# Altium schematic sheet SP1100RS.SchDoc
size D; SheetNumber: 0; SheetTotal: 0
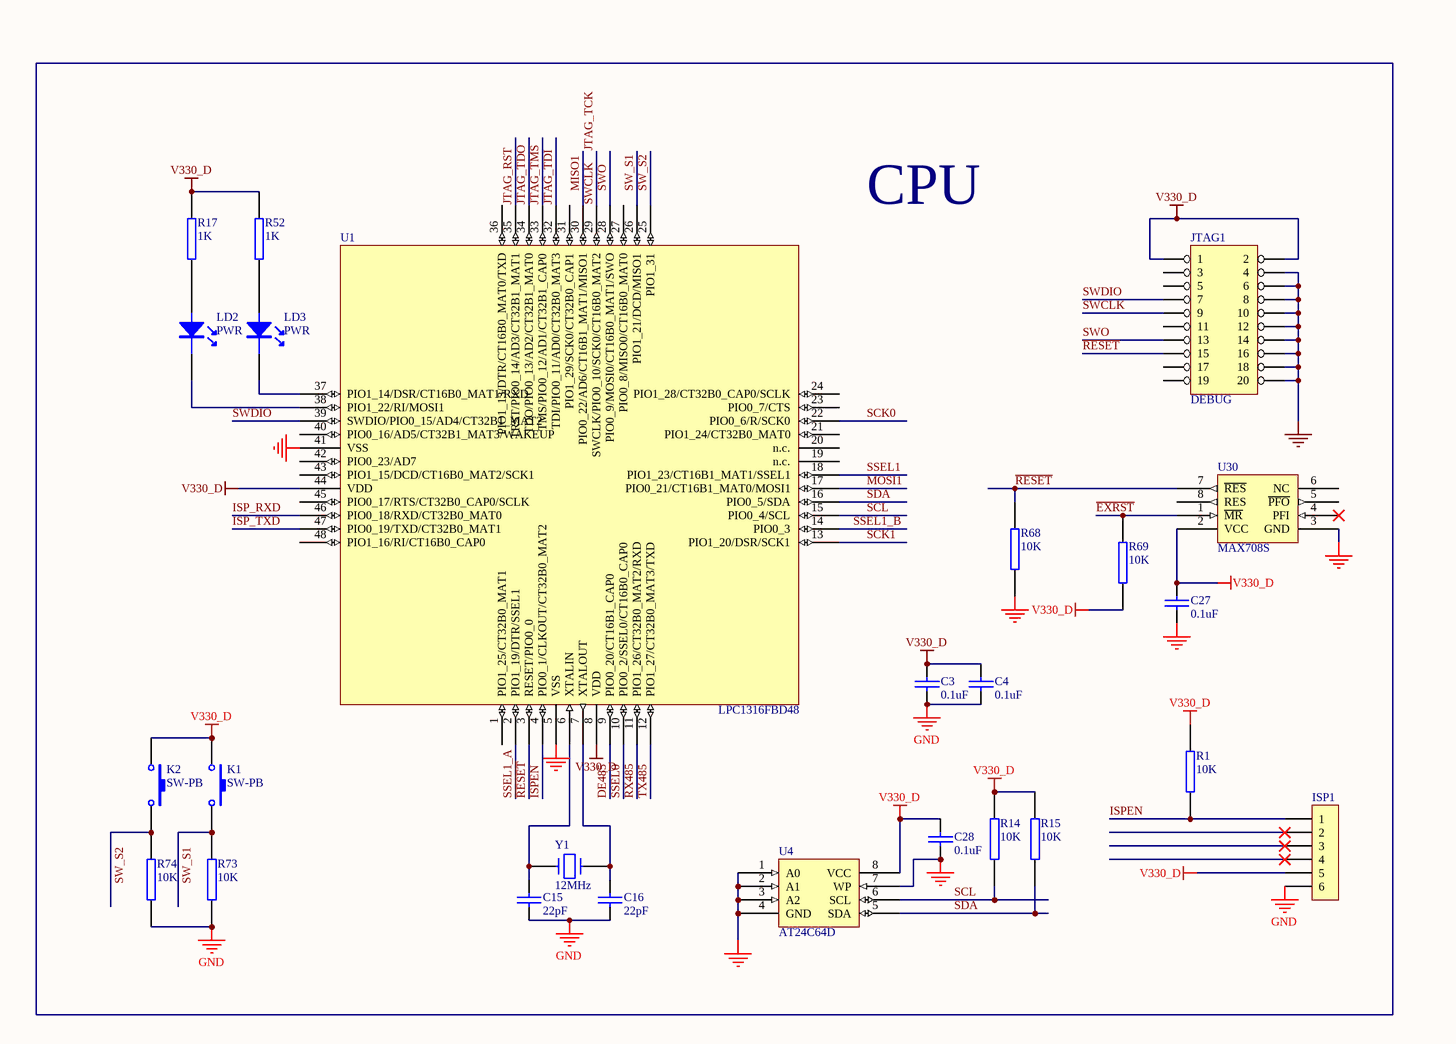
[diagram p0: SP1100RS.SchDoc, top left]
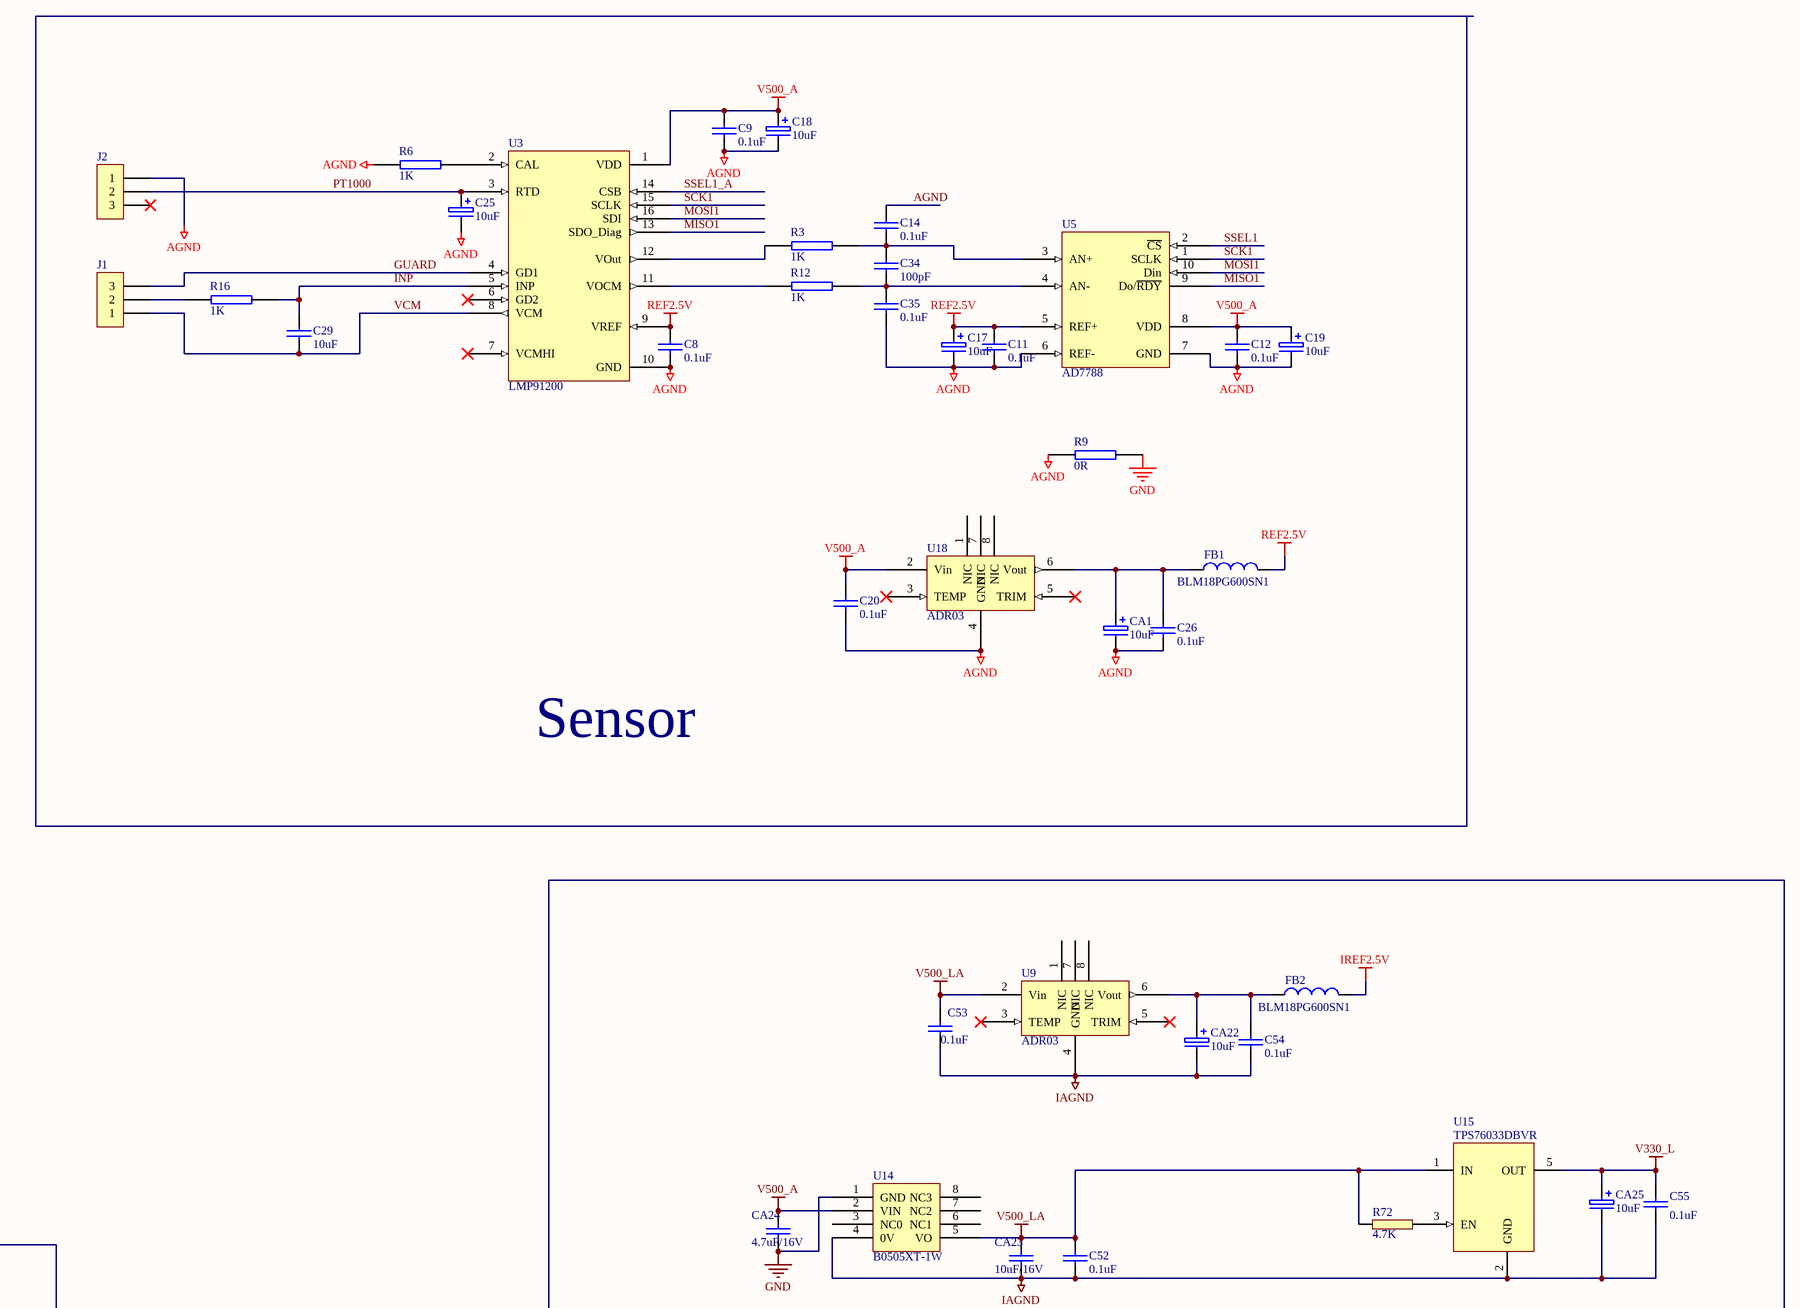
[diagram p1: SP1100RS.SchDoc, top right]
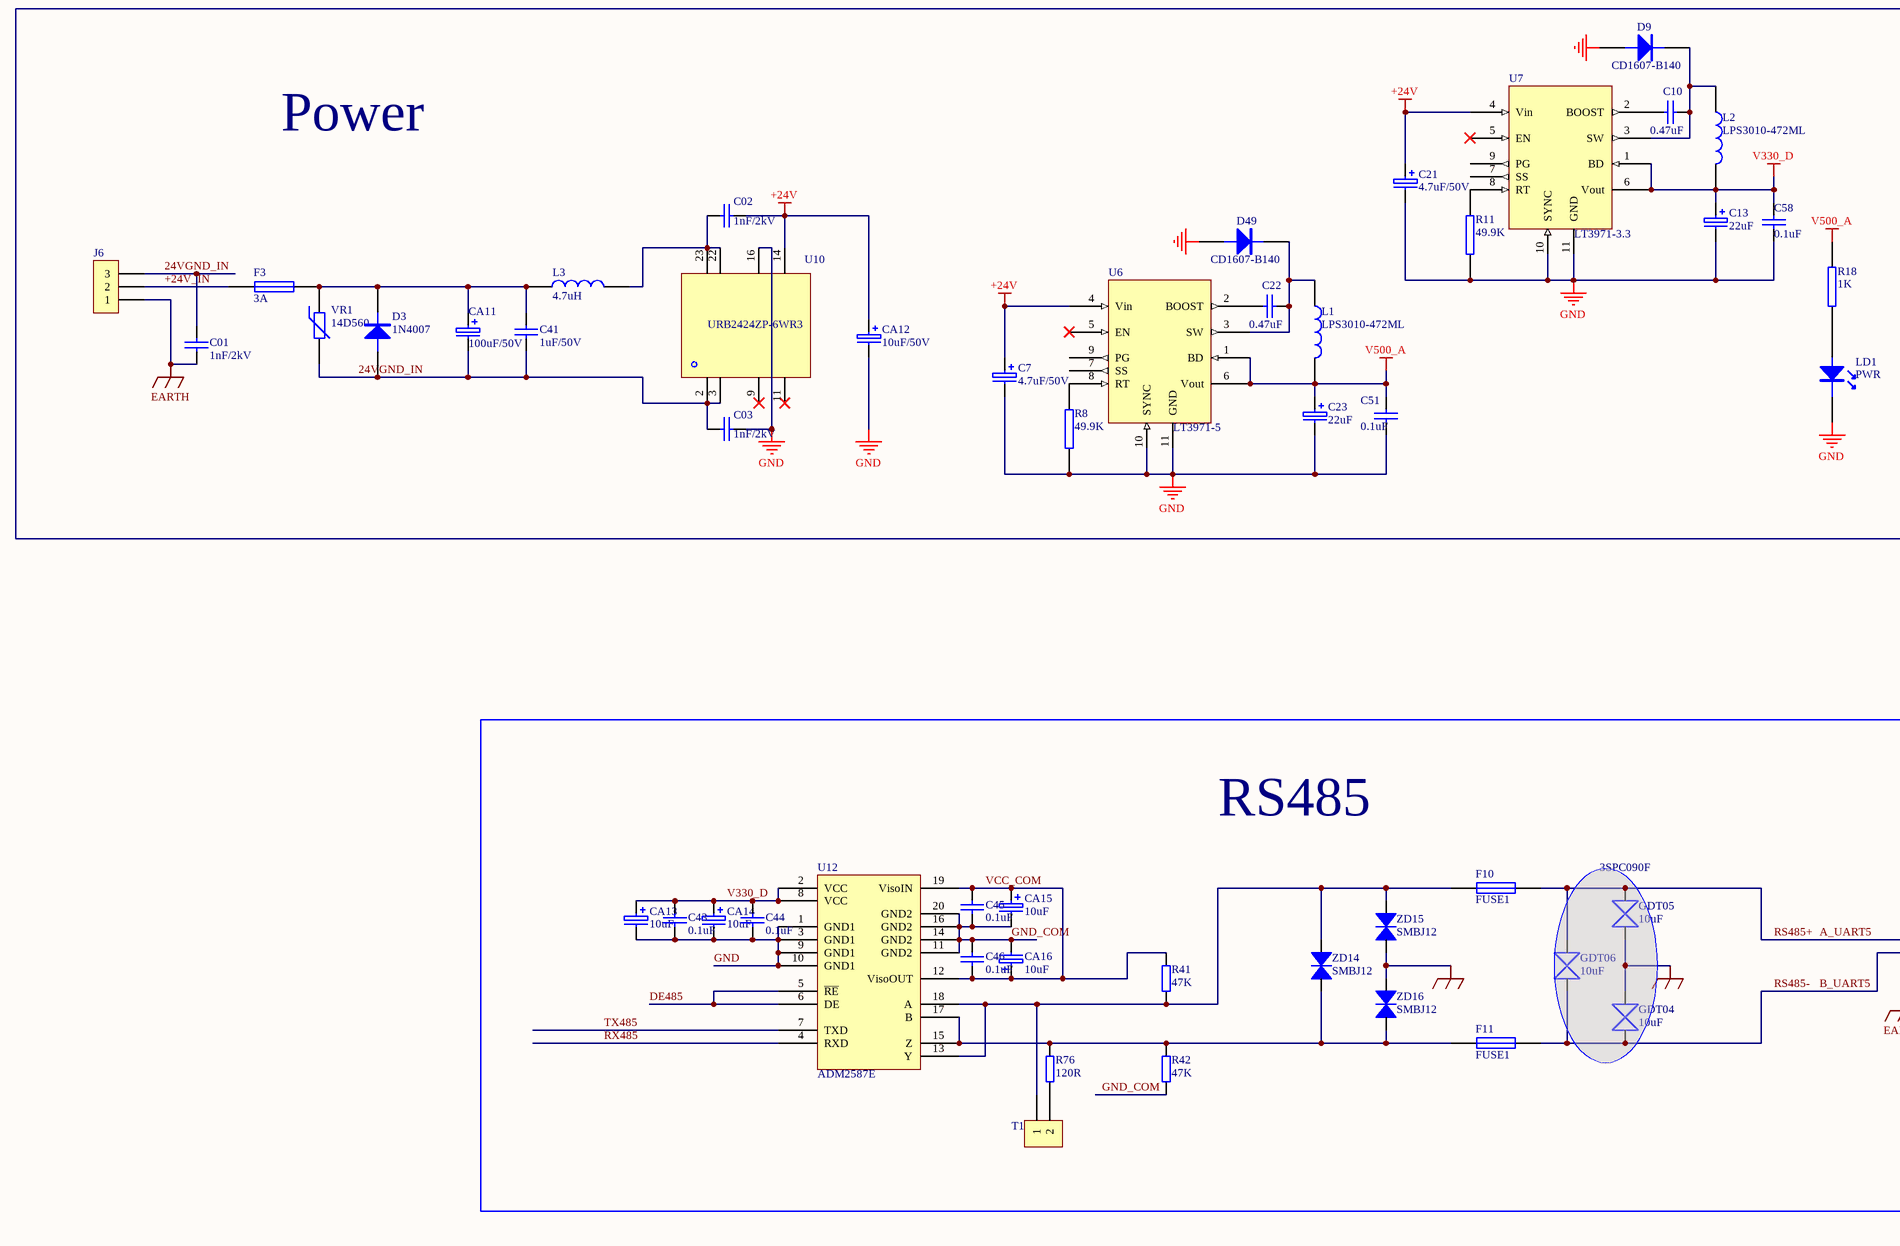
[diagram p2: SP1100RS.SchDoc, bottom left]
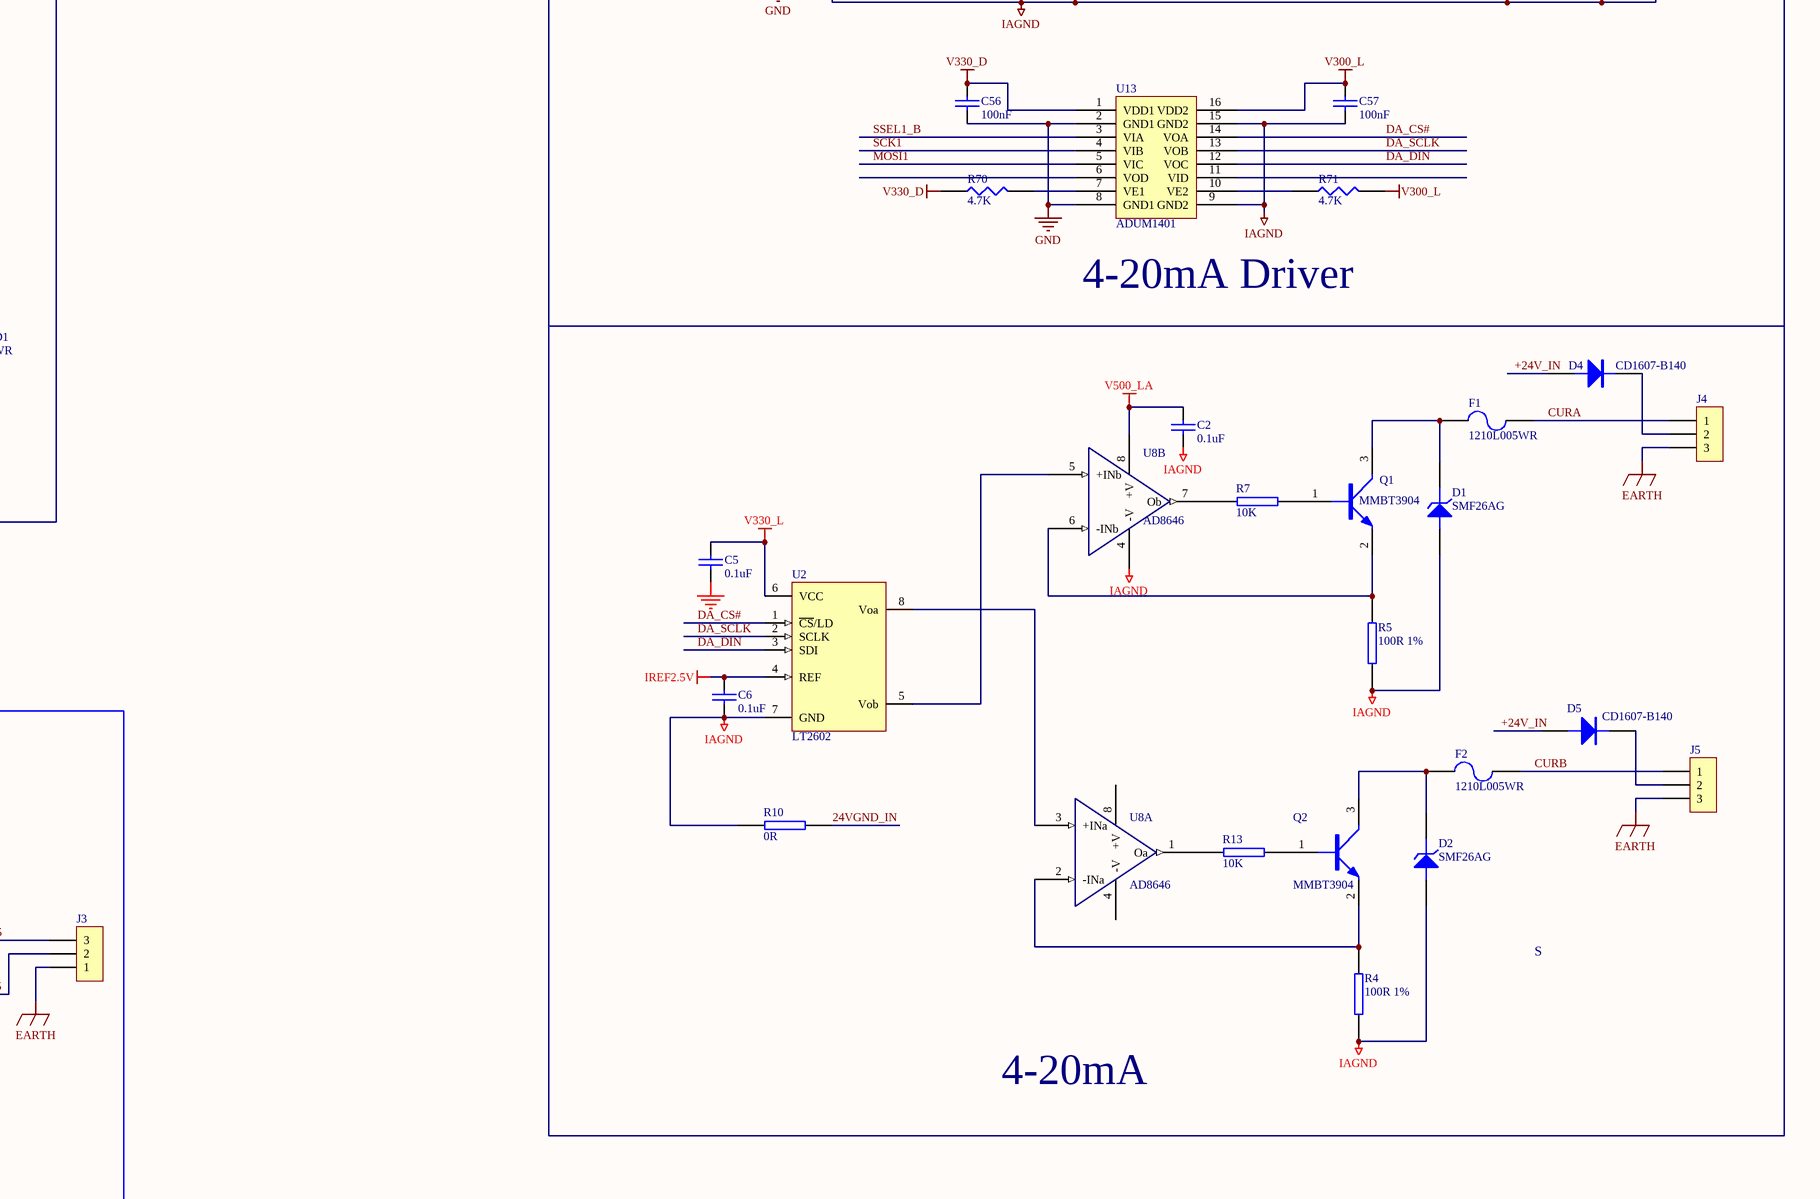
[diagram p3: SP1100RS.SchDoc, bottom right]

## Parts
C01  1nF/2kV
C2  0.1uF  [0603]
C02  1nF/2kV
C3  0.1uF  [0603]
C03  1nF/2kV
C4  0.1uF  [0603]
C5  0.1uF  [0603A]
C6  0.1uF  [0603A]
C7  4.7uF/50V  [1206C]
C8  0.1uF  [0603A]
C9  0.1uF  [0603]
C10  0.47uF  [0603]
C11  0.1uF  [0603]
C12  0.1uF  [0603]
C13  22uF  [1206C]
C14  0.1uF  [0603]
C15  22pF  [0603]
C16  22pF  [0603]
C17  10uF  [1206C]
C18  10uF  [1206C]
C19  10uF  [1206C]
C20  0.1uF  [0603A]
C21  4.7uF/50V  [1206C]
C22  0.47uF  [0603]
C23  22uF  [1206C]
C25  10uF  [1206C]
C26  0.1uF  [0603A]
C27  0.1uF  [0402]
C28  0.1uF  [0603]
C29  10uF  [1206C]
C34  100pF  [0603]
C35  0.1uF  [0603]
C41  1uF/50V  [0603]
C43  0.1uF  [0603]
C44  0.1uF  [0603]
C45  0.1uF  [0603]
C46  0.1uF  [0603]
C51  0.1uF
C52  0.1uF
C53  0.1uF  [0603A]
C54  0.1uF
C55  0.1uF  [0603A]
C56  100nF  [0603A]
C57  100nF  [0603A]
C58  0.1uF
CA1  10uF  [1206C]
CA11  100uF/50V  [1206C]
CA12  10uF/50V  [1206C]
CA13  10uF  [1206C]
CA14  10uF  [1206C]
CA15  10uF  [1206C]
CA16  10uF  [1206C]
CA22  10uF  [1206C]
CA23  10uF/16V
CA24  4.7uF/16V
CA25  10uF  [1206C]
D1  SMF26AG  [1206D]
D2  SMF26AG  [1206D]
D3  1N4007  [1206D]
D4  CD1607-B140  [1206D]
D5  CD1607-B140  [1206D]
D9  CD1607-B140  [1206D]
D49  CD1607-B140  [1206D]
F1  1210L005WR  [1206]
F2  1210L005WR  [1206]
F3  3A
F10  FUSE1
F11  FUSE1
FB1  BLM18PG600SN1  [0402-A]
FB2  BLM18PG600SN1  [0402-A]
GDT04  10uF  [1812]
GDT05  10uF  [1812]
GDT06  10uF  [1812]
ISP1  (no value)  [PH3-S]
J1  (no value)
J2  (no value)
J3  (no value)
J4  (no value)
J5  (no value)
J6  (no value)
JTAG1  DEBUG  [IDC20]
K1  SW-PB  [SPST-2]
K2  SW-PB  [SPST-2]
L1  LPS3010-472ML  [LPS3010]
L2  LPS3010-472ML  [LPS3010]
L3  4.7uH  [LPS3010]
LD1  PWR  [0603]
LD2  PWR  [0603]
LD3  PWR  [0603]
Q1  MMBT3904  [SOT-23]
Q2  MMBT3904  [SOT-23]
R1  10K  [0603]
R3  1K  [0603]
R4  100R 1%  [0603]
R5  100R 1%  [0603]
R6  1K  [0603]
R7  10K  [0603]
R8  49.9K  [0603]
R9  0R  [0603]
R10  0R  [0603]
R11  49.9K  [0603]
R12  1K  [0603]
R13  10K  [0603]
R14  10K  [0603]
R15  10K  [0603]
R16  1K  [0603]
R17  1K  [0603]
R18  1K  [0603]
R41  47K  [0603]
R42  47K  [0603]
R52  1K  [0603]
R68  10K  [0603]
R69  10K  [0603]
R70  4.7K  [0603A]
R71  4.7K  [0603A]
R72  4.7K  [0603A]
R73  10K  [0603]
R74  10K  [0603]
R76  120R  [0603]
T1  (no value)
U1  LPC1316FBD48  [0603]
U2  LT2602  [0603]
U3  LMP91200  [0603]
U4  AT24C64D  [SO-8]
U5  AD7788  [AD7788BRM]
U6  LT3971-5  [0603]
U7  LT3971-3.3  [0603]
U8  AD8646  [0603]  (parts A,B of 2)
U9  ADR03  [SO-8]
U10  URB2424ZP-6WR3
U12  ADM2587E  [SOL-20]
U13  ADUM1401
U14  B0505XT-1W
U15  TPS76033DBVR  [SOT23-5A]
U18  ADR03  [SO-8]
U30  MAX708S  [SO-8]
VR1  14D560  [6-0805_N]
Y1  12MHz  [CY5.4X4.6]
ZD14  SMBJ12  [ZD]
ZD15  SMBJ12  [ZD]
ZD16  SMBJ12  [ZD]

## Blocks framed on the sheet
CPU: C3 C4 C15 C16 C27 C28 ISP1 JTAG1 K1 K2 LD2 LD3 R1 R14 R15 R17 R52 R68 R69 R73 R74 U1 U4 U30 Y1
Power: C01 C02 C03 C7 C10 C13 C21-C23 C41 C51 C58 CA11 CA12 D3 D9 D49 F3 J6 L1-L3 LD1 R8 R11 R18 U6 U7 U10 VR1
RS485: C43-C46 CA13-CA16 F10 F11 GDT04 GDT05 GDT06 J3 R41 R42 R76 T1 U12 ZD14-ZD16

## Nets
+24V: C02.1 C7.1 C21.1 CA12.1 U6.4(Vin) U7.4(Vin) U10.14
AGND: C8.2 C9.2 C11.2 C12.2 C14.1 C17.2 C18.2 C19.2 C20.2 C25.2 C26.2 C35.2 CA1.2 J2.1 R6.2 R9.2 U3.10(GND) U5.6(REF-) U5.7(GND) U18.4(GND)
EARTH: C01.2 GDT04.2 GDT05.1 J3.1 J4.3 J5.3 J6.1 ZD15.2 ZD16.1
GND: C03.1 C3.2 C4.2 C7.2 C13.2 C15.2 C16.2 C21.2 C23.2 C27.2 C28.2 C43.2 C44.2 C51.2 C56.2 C58.2 CA12.2 CA13.2 CA14.2 CA24.2 D9.1(A) D49.1(A) ISP1.6 JTAG1.4 JTAG1.6 JTAG1.8 JTAG1.10 JTAG1.12 JTAG1.14 JTAG1.16 JTAG1.18 JTAG1.20 LD1.K R8.2 R9.1 R11.2 R68.1 R73.2 R74.2 U1.5(VSS) U1.41(VSS) U4.1(A0) U4.2(A1) U4.3(A2) U4.4(GND) U4.7(WP) U6.10(SYNC) U6.11(GND) U7.10(SYNC) U7.11(GND) U10.16 U12.1(GND1) U12.3(GND1) U12.9(GND1) U12.10(GND1) U13.2(GND1) U13.8(GND1) U14.1(GND) U30.3(GND)
IAGND: C2.2 C6.2 C52.2 C53.2 C54.2 C55.2 C57.2 CA22.2 CA23.2 CA25.2 D1.1(A) D2.1(A) R4.2 R5.2 R10.1 U2.7(GND) U8.4(-V) U9.4(GND) U13.9(GND2) U13.15(GND2) U14.4(0V) U15.2(GND)
IREF2.5V: C6.1 FB2.2 U2.4(REF)
L_GND: C5.2
NIC: U9.1(NIC) U9.7(NIC) U9.8(NIC) U18.1(NIC) U18.7(NIC) U18.8(NIC)
REF2.5V: C8.1 C11.1 C17.1 FB1.2 U3.9(VREF) U5.5(REF+)
V300_L: C57.1 R71.2 U13.16(VDD2)
V330_D: C3.1 C4.1 C13.1 C27.1 C28.1 C43.1 C44.1 C56.1 C58.1 CA13.1 CA14.1 ISP1.5 JTAG1.1 JTAG1.2 K1.1 K2.1 L2.2 R1.2 R14.2 R15.2 R17.2 R52.2 R69.1 R70.1 U1.8(VDD) U1.44(VDD) U4.8(VCC) U7.1(BD) U7.6(Vout) U12.2(VCC) U12.8(VCC) U13.1(VDD1) U30.2(VCC)
V330_L: C5.1 C55.1 CA25.1 U2.6(VCC) U15.5(OUT)
V500_A: C9.1 C12.1 C18.1 C19.1 C20.1 C23.1 C51.1 CA24.1 L1.2 R18.2 U3.1(VDD) U5.8(VDD) U6.1(BD) U6.6(Vout) U14.2(VIN) U18.2(Vin)
V500_LA: C2.1 C52.1 C53.1 CA23.1 R72.1 U8.8(+V) U9.2(Vin) U14.5(VO) U15.1(IN)
24VGND_IN: C01.1 C03.2 C41.2 CA11.2 D3.1(A) J6.3 R10.2 U10.2 U10.3 VR1.2
+24V_IN: D4.1(A) D5.1(A) F3.1 J6.2
A_UART5: F10.2 GDT05.2 GDT06.2 J3.3  [also labelled RS485+]
B_UART5: F11.2 GDT04.1 GDT06.1 J3.2  [also labelled RS485-]
CURA: F1.2 J4.1
CURB: F2.2 J5.1
DA_CS#: U2.1(~{CS}/LD) U13.14(VOA)
DA_DIN: U2.3(SDI) U13.12(VOC)
DA_SCLK: U2.2(SCLK) U13.13(VOB)
DE485: U1.9(PIO0_20/CT16B1_CAP0) U12.5(~{RE}) U12.6(DE)
~{EXRST}: R69.2 U30.1(~{MR})
GND_COM: C45.2 C46.1 CA15.2 CA16.2 R42.2 U12.11(GND2) U12.14(GND2) U12.16(GND2) U12.20(GND2)
GUARD: J1.3 U3.4(GD1)
INP: C29.1 R16.1 U3.5(INP)
ISP_RXD: U1.46(PIO0_18/RXD/CT32B0_MAT0)
ISP_TXD: U1.47(PIO0_19/TXD/CT32B0_MAT1)
ISPEN: ISP1.1 R1.1 U1.4(PIO0_1/CLKOUT/CT32B0_MAT2)
JTAG_RST: U1.35(TRST/PIO0_14/AD3/CT32B1_MAT1)
JTAG_TCK: JTAG1.9 U1.29(SWCLK/PIO0_10/SCK0/CT16B0_MAT2)  [also labelled SWCLK]
JTAG_TDI: U1.32(TDI/PIO0_11/AD0/CT32B0_MAT3)
JTAG_TDO: U1.34(TDO/PIO0_13/AD2/CT32B1_MAT0)
JTAG_TMS: U1.33(TMS/PIO0_12/AD1/CT32B1_CAP0)
MISO1: U1.30(PIO0_22/AD6/CT16B1_MAT1/MISO1) U3.13(SDO_Diag) U5.9(Do/~{RDY})
MOSI1: U1.17(PIO0_21/CT16B1_MAT0/MOSI1) U3.16(SDI) U5.10(Din) U13.5(VIC)
PT1000: C25.1 J2.2 U3.3(RTD)
~{RESET}: JTAG1.15 R68.2 U1.3(RESET/PIO0_0) U30.7(~{RES})
RX485: U1.11(PIO1_26/CT32B0_MAT2/RXD) U12.4(RXD)
SCK0: U1.22(PIO0_6/R/SCK0)
SCK1: U1.13(PIO1_20/DSR/SCK1) U3.15(SCLK) U5.1(SCLK) U13.4(VIB)
SCL: R14.1 U1.15(PIO0_4/SCL) U4.6(SCL)
SDA: R15.1 U1.16(PIO0_5/SDA) U4.5(SDA)
SSEL0: U1.10(PIO0_2/SSEL0/CT16B0_CAP0)
SSEL1: U1.18(PIO1_23/CT16B1_MAT1/SSEL1) U5.2(~{CS})
SSEL1_A: U1.2(PIO1_19/DTR/SSEL1) U3.14(CSB)
SSEL1_B: U1.14(PIO0_3) U13.3(VIA)
SW_S1: K1.2 R73.1 U1.26(PIO1_21/DCD/MISO1)
SW_S2: K2.2 R74.1 U1.25(PIO1_31)
SWDIO: JTAG1.7 U1.39(SWDIO/PIO0_15/AD4/CT32B1_MAT2)
SWO: JTAG1.13 U1.28(PIO0_9/MOSI0/CT16B0_MAT1/SWO)
TX485: U1.12(PIO1_27/CT32B0_MAT3/TXD) U12.7(TXD)
VCC_COM: C45.1 C46.2 CA15.1 CA16.1 R41.1 U12.12(VisoOUT) U12.19(VisoIN)
VCM: C29.2 J1.1 U3.8(VCM)
NetC02_2: C02.2 L3.2 U10.22 U10.23
NetC10_1: C10.1 U7.2(BOOST)
NetC10_2: C10.2 D9.2(K) L2.1 U7.3(SW)
NetC14_2: C14.2 C34.1 R3.1 U5.3(AN+)
NetC15_1: C15.1 U1.6(XTALIN) Y1.1
NetC16_1: C16.1 U1.7(XTALOUT) Y1.2
NetC22_1: C22.1 U6.2(BOOST)
NetC22_2: C22.2 D49.2(K) L1.1 U6.3(SW)
NetC26_1: C26.1 CA1.1 FB1.1 U18.6(Vout)
NetC34_2: C34.2 C35.1 R12.1 U5.4(AN-)
NetC41_1: C41.1 CA11.1 D3.2(K) F3.2 L3.1 VR1.1
NetC54_1: C54.1 CA22.1 FB2.1 U9.6(Vout)
NetD1_2: D1.2(K) F1.1 Q1.3(C)
NetD2_2: D2.2(K) F2.1 Q2.3(C)
NetD4_2: D4.2(K) J4.2
NetD5_2: D5.2(K) J5.2
NetF10_1: F10.1 R41.2 T1.1 U12.13(Y) U12.18(A) ZD14.1 ZD15.1
NetF11_1: F11.1 R42.1 R76.1 U12.15(Z) U12.17(B) ZD14.2 ZD16.2
NetJ1_2: J1.2 R16.2
NetLD1_A: LD1.A R18.1
NetLD2_A: LD2.A R17.1
NetLD2_K: LD2.K U1.38(PIO1_22/RI/MOSI1)
NetLD3_A: LD3.A R52.1
NetLD3_K: LD3.K U1.37(PIO1_14/DSR/CT16B0_MAT1/RXD)
NetQ1_1: Q1.1(B) R7.2
NetQ1_2: Q1.2(E) R5.1 U8.6(-INb)
NetQ2_1: Q2.1(B) R13.2
NetQ2_2: Q2.2(E) R4.1 U8.2(-INa)
NetR3_2: R3.2 U3.12(VOut)
NetR6_1: R6.1 U3.2(CAL)
NetR7_1: R7.1 U8.7(Ob)
NetR8_1: R8.1 U6.8(RT)
NetR11_1: R11.1 U7.8(RT)
NetR12_2: R12.2 U3.11(VOCM)
NetR13_1: R13.1 U8.1(Oa)
NetR70_2: R70.2 U13.7(VE1)
NetR71_1: R71.1 U13.10(VE2)
NetR72_2: R72.2 U15.3(EN)
NetR76_2: R76.2 T1.2
NetU2_5: U2.5(Vob) U8.5(+INb)
NetU2_8: U2.8(Voa) U8.3(+INa)

Not connected (* = marked no-connect by the designer): ISP1 2* 3* 4*; J2 3*; JTAG1 3 5 11 17 19; U1 1(PIO1_25/CT32B0_MAT1) 19(n.c.) 20(n.c.) 21(PIO1_24/CT32B0_MAT0) 23(PIO0_7/CTS) 24(PIO1_28/CT32B0_CAP0/SCLK) 27(PIO0_8/MISO0/CT16B0_MAT0) 31(PIO1_29/SCK0/CT32B0_CAP1) 36(PIO1_13/DTR/CT16B0_MAT0/TXD) 40(PIO0_16/AD5/CT32B1_MAT3/WAKEUP) 42(PIO0_23/AD7) 43(PIO1_15/DCD/CT16B0_MAT2/SCK1) 45(PIO0_17/RTS/CT32B0_CAP0/SCLK) 48(PIO1_16/RI/CT16B0_CAP0); U3 6(GD2)* 7(VCMHI)*; U6 5(EN)* 7(SS) 9(PG); U7 5(EN)* 7(SS) 9(PG); U9 3(TEMP)* 5(TRIM)*; U10 9* 11*; U13 6(VOD) 11(VID); U14 3(NC0) 6(NC1) 7(NC2) 8(NC3); U18 3(TEMP)* 5(TRIM)*; U30 4(PFI)* 5(~{PFO}) 6(NC) 8(RES)

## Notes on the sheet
- Sensor
- 4-20mA Driver
- (near GDT05) 3SPC090F
- S
- 4-20mA

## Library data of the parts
C01 C2 C02 C3 C03-C6 C8-C12 C14-C16 C20 C22 C26-C29 C34 C35 C41 C51-C58 CA23 CA24 = CAP: Capacitor
C7 C13 C17-C19 C21 C23 C25 CA1 CA11-CA16 CA22 CA25 = C: 极性电容
C43-C46 = CA: 电容
D1 D2 = ZENER3: Zener Diode
D3-D5 D9 D49 = DIODE
F1 F2 = FUSE2: Fuse
F3 F10 F11 = FUSE1: Fuse
FB1 FB2 = Inductor: Code_IEC: 1005; Value: 10mH
GDT04 GDT05 GDT06 = BT90
ISP1 = CON6: Connector
J1-J6 = CON3: Connector
JTAG1 = HEADER 10X2
K1 K2 = SW-PB: Switch
L1-L3 = INDUCTOR
LD1-LD3 = LED
R1 R3-R18 R52 R68 R69 R73 R74 = RES2
R41 R42 R76 = RE: 电阻
R70 R71 = RES1
R72 = RES5
T1 = CON2: Connector
U4 = 24C01/02/04/08/16
U6 U7 = LT3971
U9 U18 = ADR02
U15 = TPS76033
U30 = SP708
VR1 = Res Varistor: Varistor (Voltage-Sensitive Resistor)
Y1 = CRYSTAL
ZD14-ZD16 = SMBJ: 瞬变抑制二极管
